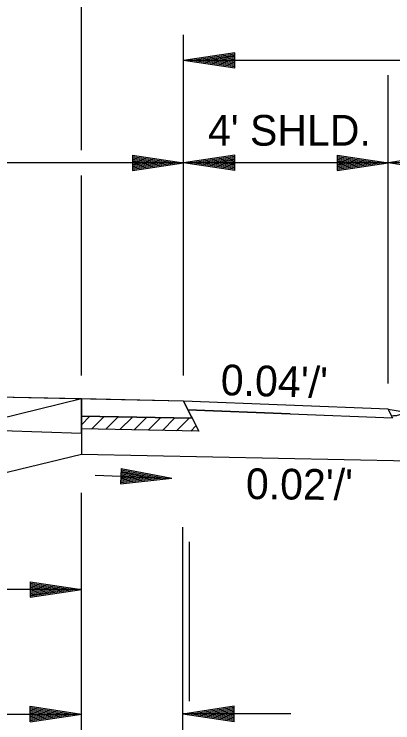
# Model space of a CAD drawing. Extents: x -900 to 15312, y 1857 to 2945.
# Drawn here: x -392.5 to -318.4, y 2161.8 to 2300.3 of the extents above; entities that cross this region are included whole.
import ezdxf

# ---------------------------------------------------------------- set-up
doc = ezdxf.new("R2010")
doc.units = 0
for name, color, linetype in [('Default', 7, 'Continuous'), ('R_Annotation', 7, 'Continuous'), ('R_Dimension', 7, 'Continuous')]:
    doc.layers.add(name, color=color, linetype=linetype)

msp = doc.modelspace()

# ---------------------------------------------------------------- linework, layer by layer
at = {"layer": 'Default'}
for p, q in [((-379.31, 2225.11), (-469.31, 2226.91)), ((-359.31, 2224.71), (-379.31, 2225.11)), ((-379.31, 2225.11), (-379.31, 2221.77)), ((-358.46, 2223), (-359.31, 2224.71)), ((-357.62, 2221.34), (-358.46, 2223)), ((-379.31, 2221.77), (-357.62, 2221.34)), ((-379.31, 2220.07), (-377.64, 2221.74)), ((-377.32, 2219.23), (-374.87, 2221.68)), ((-374.54, 2219.18), (-372.09, 2221.63)), ((-371.77, 2219.12), (-369.32, 2221.57)), ((-369, 2219.06), (-366.55, 2221.52)), ((-366.23, 2219.01), (-363.77, 2221.46)), ((-363.45, 2218.95), (-361, 2221.41)), ((-360.68, 2218.9), (-358.23, 2221.35)), ((-357.91, 2218.84), (-356.89, 2219.86))]:
    msp.add_line(p, q, dxfattribs=at)
for points in [[(-379.31, 2218.42), (-379.31, 2219.27), (-379.31, 2221.77), (-379.31, 2225.11)], [(-512.59, 2221.78), (-463.54, 2220.63), (-394.78, 2218.98), (-379.31, 2218.42)]]:
    msp.add_lwpolyline(points, dxfattribs=at)
at = {"layer": 'R_Annotation'}
for p, q in [((-359.31, 2224.71), (-469.31, 2226.91)), ((-379.31, 2225.11), (-379.31, 2214.27)), ((-359.31, 2224.71), (-356.36, 2218.81)), ((-319.31, 2223.11), (-359.31, 2224.71)), ((-338.46, 2222.2), (-358.46, 2223)), ((-319.31, 2223.11), (-318.46, 2221.4)), ((-319.31, 2223.11), (-159.31, 2196.44)), ((-357.62, 2221.34), (-379.31, 2221.77)), ((-356.36, 2218.81), (-379.31, 2219.27)), ((-250.88, 2211.7), (-379.31, 2214.27))]:
    msp.add_line(p, q, dxfattribs=at)
msp.add_open_spline([(-316.26, 2222.6), (-316.29, 2222.56), (-316.41, 2222.41), (-316.53, 2222.32), (-316.85, 2222.14), (-317.05, 2222.04), (-317.55, 2221.88), (-317.83, 2221.81), (-318.27, 2221.78), (-318.42, 2221.78), (-318.56, 2221.79)], degree=3, dxfattribs=at)
at = {"layer": 'R_Dimension'}
for p, q in [((-379.28, 2273.74), (-379.24, 2351.84)), ((-359.31, 2271.24), (-359.31, 2296.24)), ((-349.31, 2292.74), (-359.31, 2291.24)), ((-349.31, 2292.49), (-357.64, 2291.24)), ((-349.31, 2289.74), (-349.31, 2292.74)), ((-159.31, 2291.24), (-359.31, 2291.24)), ((-349.31, 2289.74), (-359.31, 2291.24)), ((-349.31, 2289.99), (-357.64, 2291.24)), ((-349.31, 2292.23), (-355.92, 2291.24)), ((-349.31, 2290.24), (-355.92, 2291.24)), ((-349.31, 2291.98), (-354.25, 2291.24)), ((-349.31, 2290.49), (-354.25, 2291.24)), ((-349.31, 2291.73), (-352.56, 2291.24)), ((-349.31, 2290.75), (-352.56, 2291.24)), ((-349.31, 2291.47), (-350.89, 2291.24)), ((-349.31, 2291), (-350.89, 2291.24)), ((-319.31, 2228.11), (-319.31, 2288.36)), ((-369.31, 2272.74), (-359.31, 2271.24)), ((-369.31, 2272.74), (-369.31, 2269.74)), ((-369.31, 2272.49), (-360.98, 2271.24)), ((-369.31, 2272.23), (-362.7, 2271.24)), ((-369.31, 2271.98), (-364.36, 2271.24)), ((-369.31, 2271.72), (-366.06, 2271.24)), ((-349.31, 2272.74), (-359.31, 2271.24)), ((-349.31, 2272.49), (-357.64, 2271.24)), ((-349.31, 2272.23), (-355.92, 2271.24)), ((-349.31, 2271.98), (-354.25, 2271.24)), ((-349.31, 2271.73), (-352.56, 2271.24)), ((-349.31, 2269.74), (-349.31, 2272.74)), ((-329.31, 2272.74), (-319.31, 2271.24)), ((-329.31, 2272.74), (-329.31, 2269.74)), ((-329.31, 2272.49), (-320.98, 2271.24)), ((-329.31, 2272.23), (-322.7, 2271.24)), ((-329.31, 2271.98), (-324.36, 2271.24)), ((-329.31, 2271.72), (-326.06, 2271.24)), ((-309.31, 2272.74), (-319.31, 2271.24)), ((-250.88, 2271.24), (-687.73, 2271.24)), ((-369.31, 2271.47), (-367.73, 2271.24)), ((-369.31, 2269.74), (-359.31, 2271.24)), ((-369.31, 2270.75), (-366.06, 2271.24)), ((-369.31, 2270.24), (-362.7, 2271.24)), ((-369.31, 2269.99), (-360.98, 2271.24)), ((-369.31, 2270.49), (-364.36, 2271.24)), ((-369.31, 2271), (-367.73, 2271.24)), ((-359.31, 2229.71), (-359.31, 2271.24)), ((-349.31, 2269.74), (-359.31, 2271.24)), ((-349.31, 2269.99), (-357.64, 2271.24)), ((-349.31, 2270.24), (-355.92, 2271.24)), ((-349.31, 2270.49), (-354.25, 2271.24)), ((-349.31, 2270.75), (-352.56, 2271.24)), ((-349.31, 2271.47), (-350.89, 2271.24)), ((-349.31, 2271), (-350.89, 2271.24)), ((-329.31, 2271.47), (-327.73, 2271.24)), ((-329.31, 2269.74), (-319.31, 2271.24)), ((-329.31, 2270.75), (-326.06, 2271.24)), ((-329.31, 2270.24), (-322.7, 2271.24)), ((-329.31, 2269.99), (-320.98, 2271.24)), ((-329.31, 2270.49), (-324.36, 2271.24)), ((-329.31, 2271), (-327.73, 2271.24)), ((-309.31, 2269.74), (-319.31, 2271.24)), ((-379.31, 2229.71), (-379.29, 2268.74)), ((-379.31, 2225.11), (-413.76, 2216.75)), ((-359.31, 2224.71), (-358.46, 2223)), ((-319.31, 2223.11), (-359.31, 2224.71)), ((-358.46, 2223), (-318.46, 2221.4)), ((-318.46, 2221.4), (-319.31, 2223.11)), ((-379.31, 2214.27), (-413.76, 2205.91)), ((-371.54, 2211.54), (-371.66, 2208.54)), ((-371.57, 2210.78), (-366.66, 2209.84)), ((-371.56, 2211.03), (-365, 2209.78)), ((-371.55, 2211.29), (-363.28, 2209.71)), ((-371.54, 2211.54), (-361.61, 2209.64)), ((-376.6, 2210.24), (-361.61, 2209.64)), ((-371.66, 2208.54), (-361.61, 2209.64)), ((-371.65, 2208.79), (-363.28, 2209.71)), ((-371.64, 2209.05), (-365, 2209.78)), ((-371.63, 2209.3), (-366.66, 2209.84)), ((-371.62, 2209.55), (-368.36, 2209.91)), ((-371.61, 2209.8), (-370.03, 2209.98)), ((-371.6, 2210.27), (-370.03, 2209.98)), ((-371.59, 2210.52), (-368.36, 2209.91)), ((-379.31, 2163.57), (-379.31, 2206.78)), ((-359.44, 2103.75), (-359.44, 2200.09)), ((-358.18, 2166.07), (-358.18, 2197.19)), ((-389.31, 2189.38), (-379.31, 2187.88)), ((-389.31, 2189.38), (-389.31, 2186.38)), ((-389.31, 2189.13), (-380.98, 2187.88)), ((-389.31, 2188.87), (-382.7, 2187.88)), ((-389.31, 2188.62), (-384.36, 2187.88)), ((-379.31, 2187.88), (-594.31, 2187.88)), ((-389.31, 2188.36), (-386.06, 2187.88)), ((-389.31, 2188.11), (-387.73, 2187.88)), ((-389.31, 2186.38), (-379.31, 2187.88)), ((-389.31, 2187.39), (-386.06, 2187.88)), ((-389.31, 2186.88), (-382.7, 2187.88)), ((-389.31, 2186.63), (-380.98, 2187.88)), ((-389.31, 2187.13), (-384.36, 2187.88)), ((-389.31, 2187.64), (-387.73, 2187.88)), ((-389.31, 2165.07), (-379.31, 2163.57)), ((-389.31, 2162.07), (-389.31, 2165.07)), ((-349.44, 2165.07), (-359.44, 2163.57)), ((-349.44, 2162.07), (-349.44, 2165.07)), ((-389.31, 2164.82), (-380.98, 2163.57)), ((-389.31, 2164.56), (-382.7, 2163.57)), ((-389.31, 2164.31), (-384.36, 2163.57)), ((-389.31, 2164.06), (-386.06, 2163.57)), ((-389.31, 2163.8), (-387.73, 2163.57)), ((-349.44, 2164.82), (-357.77, 2163.57)), ((-349.44, 2164.56), (-356.05, 2163.57)), ((-349.44, 2164.31), (-354.39, 2163.57)), ((-349.44, 2164.06), (-352.69, 2163.57)), ((-349.44, 2163.8), (-351.02, 2163.57)), ((-581.18, 2163.57), (-379.41, 2163.57)), ((-389.31, 2162.07), (-379.31, 2163.57)), ((-389.31, 2163.08), (-386.06, 2163.57)), ((-389.31, 2162.57), (-382.7, 2163.57)), ((-389.31, 2162.32), (-380.98, 2163.57)), ((-389.31, 2162.82), (-384.36, 2163.57)), ((-389.31, 2163.33), (-387.73, 2163.57)), ((-379.31, 2108.75), (-379.31, 2163.57)), ((-359.44, 2163.64), (-338.36, 2163.64)), ((-349.44, 2162.07), (-359.44, 2163.57)), ((-349.44, 2162.32), (-357.77, 2163.57)), ((-349.44, 2162.57), (-356.05, 2163.57)), ((-349.44, 2162.82), (-354.39, 2163.57)), ((-349.44, 2163.08), (-352.69, 2163.57)), ((-349.44, 2163.33), (-351.02, 2163.57))]:
    msp.add_line(p, q, dxfattribs=at)

# ---------------------------------------------------------------- texts
at = {"layer": 'R_Annotation'}
msp.add_text("4' SHLD.", height=6, dxfattribs=at).set_placement((-354.55, 2274.59))
for s, rotation, p in [("0.04'/'", 358.3978, (-352.11, 2225.87)), ("0.02'/'", 359.3505, (-347.15, 2205.57))]:
    msp.add_text(s, height=6, rotation=rotation, dxfattribs=at).set_placement(p)

doc.saveas('drawing.dxf')
